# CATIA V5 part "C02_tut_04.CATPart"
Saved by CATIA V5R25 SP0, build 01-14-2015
Part number: Part1
Bounding box of the stored display mesh (mm): x 0 to 0, y -50 to 100.45, z -30 to 49.999
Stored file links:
  E:\ashutosh\Academics\Catia\CATIA V5-6R2013_partfiles\Tutorials_ver_2\C02_tut_04.CATPart
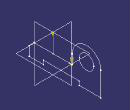
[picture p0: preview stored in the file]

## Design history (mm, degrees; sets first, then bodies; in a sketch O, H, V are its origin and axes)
Body1 (main body)
  Sketch1 on yz-plane, origin (0, 0, 0), H (0, 1, 0), V (0, 0, 1)
    line L1 (-50, -30) -> (-20, -30)
    line L2 (-20, -30) -> (-20, -22)
    line L3 (-20, -22) -> (55, -22)
    line L4 (55, -22) -> (55, -30)
    line L5 (55, -30) -> (55.45, -30)
    line L6 (55.45, -30) -> (100.45, -30)
    line L7 (100.45, -30) -> (100.45, 20)
    arc A1 centre (70.45, 20) radius 30 from (100.45, 20) to (40.45, 20) ccw
    line L8 (40.45, 20) -> (40.45, 0)
    line L9 (40.45, 0) -> (-40, 0)
    line L10 (-40, 0) -> (-50, -10)
    line L11 (-50, -10) -> (-50, -30)
    circle A2 centre (70.45, 20) radius 15
    length L1 = 30
    length L2 = 8
    length L3 = 75
    length L4 = 8
    length L5 = 0.45
    length L6 = 45
    length L7 = 50
    radius A1 = 30
    radius A2 = 15
    horizontal: L1 H, L3 H, L5 H, L6 H, L9 H
    vertical: L2 V, L4 V, L7 V, L11 V
    tangency: A1 L7, L8 A1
